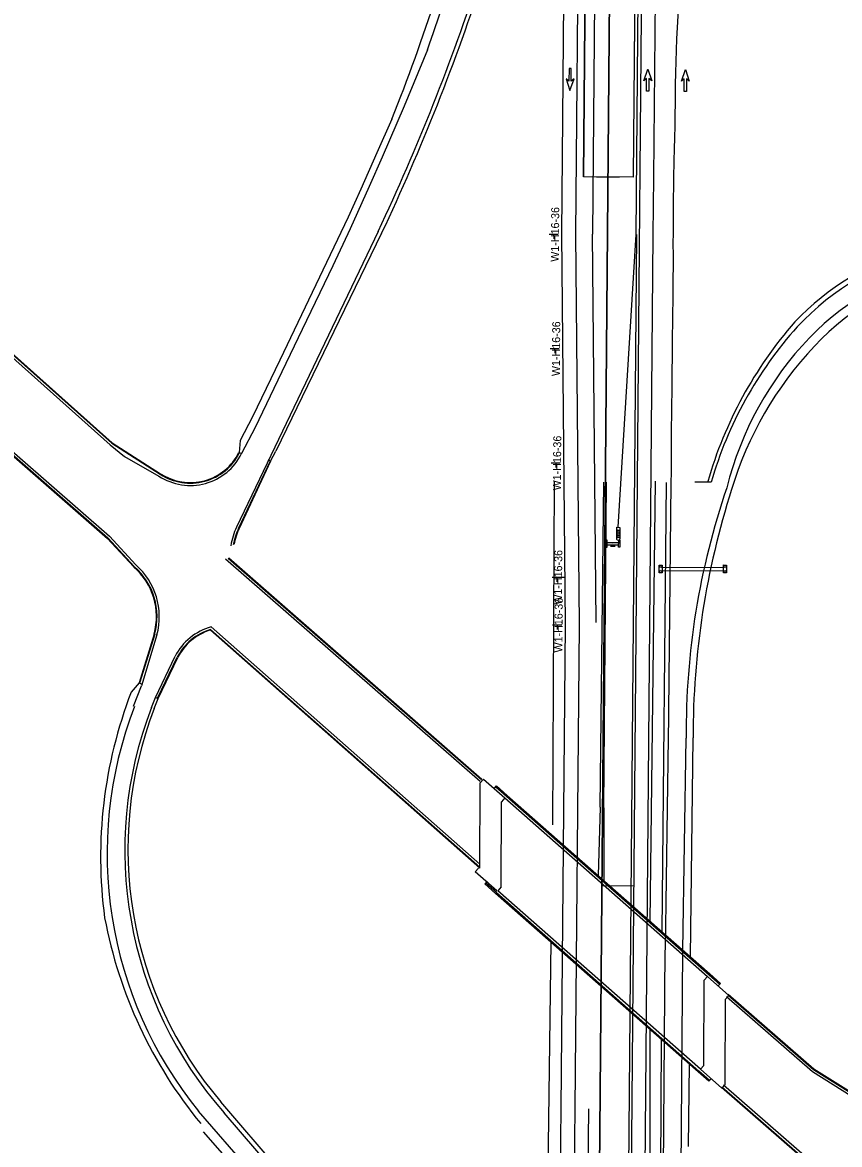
# Model space of a CAD drawing. Extents: x 1691089 to 1704871, y 694247 to 736350.
# Drawn here: x 1700893 to 1701608, y 709482 to 710464 of the extents above; entities that cross this region are included whole.
import ezdxf

# ---------------------------------------------------------------- set-up
doc = ezdxf.new("R2010")
doc.units = 0
for name, color, linetype in [('Default', 7, 'Continuous'), ('MT_P_Cells', 7, 'Continuous'), ('MT_P_Channelizing_Line', 7, 'Continuous'), ('MT_P_Drums', 7, 'Continuous'), ('MT_P_Edge_Line', 7, 'Continuous'), ('MT_P_PCB', 7, 'Continuous'), ('MT_P_Traffic_Attenuator', 7, 'Continuous'), ('MT_P_Work_Area', 7, 'Continuous'), ('PM_X_CL_Dashed', 7, 'Continuous'), ('PM_X_Edge_Line', 7, 'Continuous'), ('PV_X_Curb', 7, 'Continuous'), ('PV_X_EOP', 7, 'Continuous'), ('PV_X_Shoulder', 7, 'Continuous'), ('RW_X_CL', 7, 'Continuous'), ('SC_Scratch1', 7, 'Continuous'), ('SC_Scratch2', 7, 'Continuous'), ('SN_P_Signs', 7, 'Continuous'), ('SN_X_Truss_Overhead', 7, 'Continuous')]:
    doc.layers.add(name, color=color, linetype=linetype)

msp = doc.modelspace()

# ---------------------------------------------------------------- linework, layer by layer
at = {"layer": 'Default'}
for p, q in [((1700991.11, 709873.47), (1700991.11, 709873.47)), ((1701293.07, 709724.33), (1701293.3, 709798.79)), ((1701296.28, 709802.17), (1701293.3, 709798.79)), ((1701296.28, 709802.17), (1701315.03, 709785.63)), ((1701305.65, 709793.9), (1701307.64, 709796.15)), ((1701306.98, 709795.4), (1701316.35, 709787.13)), ((1701307.64, 709796.15), (1701317.01, 709787.88)), ((1701316.35, 709787.13), (1701493.48, 709630.96)), ((1701317.01, 709787.88), (1701494.15, 709631.71)), ((1701311.82, 709707.8), (1701312.05, 709782.26)), ((1701315.03, 709785.63), (1701312.05, 709782.26)), ((1701315.03, 709785.63), (1701492.16, 709629.46)), ((1701291.98, 709724.32), (1701289.02, 709720.93)), ((1701307.85, 709704.48), (1701289.02, 709720.93)), ((1701299.47, 709712.69), (1701297.49, 709710.44)), ((1701306.86, 709702.17), (1701297.49, 709710.44)), ((1701307.53, 709702.92), (1701298.15, 709711.19)), ((1701484, 709546), (1701306.86, 709702.17)), ((1701484.66, 709546.75), (1701307.53, 709702.92)), ((1701311.82, 709707.8), (1701308.85, 709704.42)), ((1701485.98, 709548.25), (1701308.85, 709704.42)), ((1701492.16, 709629.46), (1701489.19, 709626.08)), ((1701492.16, 709629.46), (1701510.91, 709612.92)), ((1701493.48, 709630.96), (1701502.86, 709622.69)), ((1701494.15, 709631.71), (1701503.52, 709623.44)), ((1701488.96, 709551.62), (1701489.19, 709626.08)), ((1701501.54, 709621.19), (1701503.52, 709623.44)), ((1701510.91, 709612.92), (1701507.94, 709609.55)), ((1701507.71, 709535.09), (1701507.94, 709609.55)), ((1701488.96, 709551.62), (1701485.98, 709548.25)), ((1701493.37, 709537.73), (1701484, 709546)), ((1701494.03, 709538.48), (1701484.66, 709546.75)), ((1701504.73, 709531.71), (1701485.98, 709548.25)), ((1701495.36, 709539.98), (1701493.37, 709537.73)), ((1701507.71, 709535.09), (1701504.73, 709531.71))]:
    msp.add_line(p, q, dxfattribs=at)
at = {"layer": 'MT_P_Cells'}
for p, q in [((1701370.93, 710412.57), (1701368.48, 710414.59)), ((1701368.48, 710414.59), (1701371.86, 710404.56)), ((1701371.02, 710423.57), (1701370.93, 710412.57)), ((1701373.02, 710423.55), (1701371.02, 710423.57)), ((1701372.02, 710423.56), (1701372.02, 710423.56)), ((1701372.93, 710412.55), (1701373.02, 710423.55)), ((1701436.46, 710413.01), (1701440.02, 710422.98)), ((1701438.95, 710414.99), (1701436.46, 710413.01)), ((1701438.86, 710403.99), (1701438.95, 710414.99)), ((1701440.02, 710422.98), (1701440.02, 710422.98)), ((1701440.02, 710422.98), (1701443.41, 710412.95)), ((1701440.95, 710414.97), (1701440.86, 710403.97)), ((1701443.41, 710412.95), (1701440.95, 710414.97)), ((1701469.28, 710412.73), (1701472.84, 710422.7)), ((1701471.77, 710414.7), (1701469.28, 710412.73)), ((1701471.67, 710403.71), (1701471.77, 710414.7)), ((1701472.84, 710422.7), (1701472.84, 710422.7)), ((1701472.84, 710422.7), (1701476.22, 710412.67)), ((1701473.77, 710414.69), (1701473.67, 710403.69)), ((1701476.22, 710412.67), (1701473.77, 710414.69)), ((1701371.86, 710404.56), (1701375.42, 710414.53)), ((1701375.42, 710414.53), (1701372.93, 710412.55)), ((1701371.86, 710404.56), (1701371.86, 710404.56)), ((1701440.86, 710403.97), (1701438.86, 710403.99)), ((1701439.86, 710403.98), (1701439.86, 710403.98)), ((1701473.67, 710403.69), (1701471.67, 710403.71)), ((1701472.67, 710403.7), (1701472.67, 710403.7)), ((1701404.46, 710007.09), (1701414.46, 710007)), ((1701404.48, 710009.09), (1701414.48, 710009)), ((1701411.45, 710005.53), (1701407.45, 710005.56)), ((1701408.46, 710007.05), (1701408.45, 710005.55)), ((1701409.47, 710008.04), (1701409.47, 710008.04)), ((1701410.46, 710007.03), (1701410.45, 710005.53))]:
    msp.add_line(p, q, dxfattribs=at)
for points in [[(1701403.49, 710011.09), (1701403.44, 710005.09), (1701404.44, 710005.09), (1701404.49, 710011.09)], [(1701415.49, 710010.99), (1701415.44, 710004.99), (1701414.44, 710005), (1701414.49, 710011)]]:
    msp.add_lwpolyline(points, close=True, dxfattribs=at)
at = {"layer": 'MT_P_Channelizing_Line'}
for points in [[(1701379.36, 710578.91), (1701376.78, 710278.89), (1701379.85, 709936.81)], [(1701379.85, 709936.81), (1701379.81, 709936.81), (1701376.18, 709513.9)]]:
    msp.add_lwpolyline(points, dxfattribs=at)
at = {"layer": 'MT_P_Drums'}
for p, q in [((1701391.33, 710278.81), (1701394.37, 709939.22)), ((1701422.33, 709351.5), (1701430.28, 710278.43))]:
    msp.add_line(p, q, dxfattribs=at)
at = {"layer": 'MT_P_Edge_Line'}
for p, q in [((1701445.21, 710328.34), (1701466.82, 712847.84)), ((1701444.78, 710278.3), (1701445.21, 710328.34)), ((1701437.19, 709393.09), (1701444.78, 710278.3)), ((1701364.23, 709514), (1701367.85, 709936.91))]:
    msp.add_line(p, q, dxfattribs=at)
for points in [[(1701414.35, 708961.55), (1701424.83, 709351.48), (1701474.54, 715147.93), (1701474.62, 715157.86), (1701474.71, 715167.87), (1701474.78, 715177.89), (1701474.85, 715187.92), (1701474.91, 715198.02), (1701474.96, 715207.99), (1701474.99, 715218.04), (1701475, 715228.09), (1701474.99, 715238.15), (1701474.96, 715248.3), (1701474.9, 715258.3), (1701474.81, 715268.38), (1701474.69, 715278.48), (1701474.54, 715288.57), (1701474.35, 715298.75), (1701474.12, 715308.79), (1701473.84, 715318.91), (1701473.52, 715329.03), (1701473.16, 715339.16), (1701472.74, 715349.34), (1701472.74, 715349.36)], [(1701367.85, 709936.91), (1701364.78, 710278.99), (1701390.07, 713227.64)]]:
    msp.add_lwpolyline(points, dxfattribs=at)
at = {"layer": 'MT_P_PCB'}
for p, q in [((1701429.78, 710278.47), (1701462.53, 714097.92)), ((1701414.07, 710022.33), (1701429.78, 710278.47))]:
    msp.add_line(p, q, dxfattribs=at)
at = {"layer": 'MT_P_Traffic_Attenuator'}
for p, q in [((1701412.59, 710022.34), (1701412.47, 710012.02)), ((1701412.59, 710022.34), (1701415.58, 710022.31)), ((1701415.58, 710022.31), (1701415.49, 710011.99)), ((1701415.45, 710012.96), (1701412.48, 710013.91)), ((1701415.47, 710014.54), (1701412.5, 710015.49)), ((1701412.5, 710013.05), (1701415.42, 710013.99)), ((1701412.51, 710014.64), (1701415.43, 710015.57)), ((1701415.49, 710016.09), (1701412.52, 710017.04)), ((1701412.53, 710019.27), (1701415.51, 710020.23)), ((1701415.52, 710019.18), (1701412.54, 710020.14)), ((1701415.5, 710017.64), (1701412.54, 710018.59)), ((1701412.54, 710016.19), (1701415.45, 710017.12)), ((1701412.56, 710017.74), (1701415.47, 710018.67))]:
    msp.add_line(p, q, dxfattribs=at)
msp.add_arc((1701413.99, 710012.64), 1.64, 202.38552, 336.63188, dxfattribs=at)
at = {"layer": 'MT_P_Work_Area'}
msp.add_line((1701415.21, 710328.6), (1701395.21, 710328.77), dxfattribs=at)
for points in [[(1701423.28, 715347.21), (1701423.69, 715337.24), (1701424.05, 715327.35), (1701424.37, 715317.46), (1701424.63, 715307.55), (1701424.86, 715297.71), (1701425.05, 715287.73), (1701425.2, 715277.8), (1701425.32, 715267.88), (1701425.4, 715257.94), (1701425.46, 715248.07), (1701425.49, 715238.05), (1701425.5, 715228.1), (1701425.49, 715218.14), (1701425.46, 715208.18), (1701425.41, 715198.28), (1701425.35, 715188.24), (1701425.29, 715178.26), (1701425.21, 715168.27), (1701425.13, 715158.28), (1701425.04, 715148.35), (1701383.71, 710328.87)], [(1701466.74, 715349.1), (1701466.74, 715349.09), (1701467.16, 715338.93), (1701467.53, 715328.83), (1701467.85, 715318.73), (1701468.12, 715308.64), (1701468.35, 715298.62), (1701468.54, 715288.47), (1701468.69, 715278.39), (1701468.81, 715268.32), (1701468.9, 715258.26), (1701468.96, 715248.27), (1701468.99, 715238.14), (1701469, 715228.09), (1701468.99, 715218.05), (1701468.96, 715208.01), (1701468.91, 715198.05), (1701468.85, 715187.96), (1701468.78, 715177.94), (1701468.71, 715167.92), (1701468.62, 715157.91), (1701468.54, 715147.98), (1701427.21, 710328.49)], [(1701459.42, 714084.32), (1701427.21, 710328.49), (1701383.71, 710328.87), (1701425.04, 715148.35)]]:
    msp.add_lwpolyline(points, dxfattribs=at)
at = {"layer": 'PM_X_CL_Dashed'}
msp.add_line((1701376.18, 709513.9), (1701371.88, 709153.62), dxfattribs=at)
at = {"layer": 'PM_X_Edge_Line'}
for p, q in [((1701458.1, 709832.7), (1701460.45, 710061.44)), ((1701455.32, 709652.66), (1701458.19, 709838.29)), ((1701453.58, 709431.6), (1701455.27, 709652.54)), ((1701468.96, 709431.48), (1701470.65, 709652.42)), ((1701359.3, 709110.99), (1701364.23, 709514)), ((1701388.22, 709513.8), (1701383.88, 709153.62))]:
    msp.add_line(p, q, dxfattribs=at)
for points in [[(1701464.27, 710409.79), (1701464.41, 710419.77), (1701464.64, 710429.76), (1701464.91, 710439.73), (1701465.31, 710449.71), (1701465.79, 710459.68), (1701466.41, 710469.68), (1701467.07, 710479.62), (1701468.02, 710489.55), (1701469.01, 710499.53), (1701470.02, 710509.54), (1701470.96, 710519.53), (1701471.99, 710529.45), (1701473.06, 710539.38), (1701474.3, 710549.25), (1701474.72, 710552.39)], [(1701460.45, 710061.44), (1701460.55, 710070.28), (1701460.61, 710080.28), (1701460.68, 710090.28), (1701460.78, 710100.3), (1701460.81, 710110.3), (1701460.92, 710120.29), (1701461, 710130.29), (1701461.12, 710140.29), (1701461.19, 710150.29), (1701461.54, 710180.28), (1701461.66, 710190.28), (1701461.79, 710200.28), (1701461.9, 710210.28), (1701462.01, 710220.28), (1701462.09, 710230.28), (1701462.3, 710260.31), (1701462.24, 710270.31), (1701462.31, 710280.28), (1701462.38, 710290.28), (1701462.44, 710300.28), (1701462.54, 710310.25), (1701462.77, 710320.26), (1701462.81, 710330.27), (1701462.98, 710340.29), (1701463, 710343.26), (1701463.29, 710353.24), (1701463.49, 710363.24), (1701463.77, 710373.24), (1701463.93, 710383.27), (1701464.1, 710393.28), (1701464.21, 710403.3), (1701464.26, 710409.81)]]:
    msp.add_lwpolyline(points, dxfattribs=at)
at = {"layer": 'PV_X_Curb'}
for p, q in [((1700971.12, 710095.92), (1701013.46, 710068.83)), ((1700971.45, 710096.29), (1701013.73, 710069.25)), ((1701109.54, 710080.32), (1701082, 710021.63)), ((1701110, 710080.1), (1701082.46, 710021.42)), ((1700990.31, 709987.7), (1700967.12, 710012.88)), ((1700990.68, 709988.04), (1700967.48, 710013.22)), ((1701008.1, 709928.91), (1700994.92, 709886.17)), ((1701008.59, 709928.78), (1700995.23, 709886.05)), ((1701057.41, 709932.42), (1701293.07, 709724.33)), ((1701057.54, 709932.98), (1701293.07, 709724.99)), ((1701011.02, 709872.9), (1701028.3, 709908.62)), ((1701011.53, 709872.7), (1701028.75, 709908.39)), ((1701584.9, 709548.09), (1701629.12, 709520.4)), ((1701585.16, 709548.52), (1701629.38, 709520.84))]:
    msp.add_line(p, q, dxfattribs=at)
for points in [[(1700673.51, 710361.66), (1700971.04, 710095.97)], [(1700673.84, 710362.04), (1700971.37, 710096.34)], [(1700628.16, 710308.99), (1700967.31, 710012.69)], [(1700628.48, 710309.37), (1700967.64, 710013.07)], [(1701072.81, 709995.47), (1701294.5, 709801.79)], [(1701073.35, 709995.67), (1701294.83, 709802.17)], [(1701510, 709613.52), (1701584.9, 709548.09)], [(1701510.33, 709613.9), (1701585.16, 709548.52)], [(1701504.52, 709532.66), (1701595.73, 709452.97)], [(1701504.84, 709533.04), (1701596.01, 709453.39)]]:
    msp.add_lwpolyline(points, dxfattribs=at)
for centre, radius, start, end in [((1701039.79, 710108.96), 48, 236.73099, 333.65872), ((1701039.79, 710108.96), 47.5, 236.73099, 333.64609), ((1701134.52, 709997), 58, 154.87152, 170.01912), ((1701134.52, 709997), 57.5, 154.87152, 169.7386), ((1700952.67, 709944.21), 57.5, 344.57519, 48.85797), ((1700952.67, 709944.21), 58, 344.57519, 48.85797), ((1701071.13, 709886.94), 48, 106.4476, 153.15416), ((1701071.13, 709886.94), 47.5, 106.78063, 153.15416)]:
    msp.add_arc(centre, radius, start, end, dxfattribs=at)
at = {"layer": 'PV_X_EOP'}
for p, q in [((1701446.54, 715148.22), (1701323.36, 700783.77)), ((1701446.54, 715148.22), (1701323.36, 700783.77)), ((1701446.54, 715148.22), (1701323.36, 700783.77)), ((1701446.54, 715148.22), (1701323.36, 700783.77)), ((1701204.1, 710281.24), (1701080.19, 710022.48)), ((1701570.63, 710197.69), (1701570.57, 710197.63)), ((1700969.71, 710094.48), (1700982.17, 710084.38)), ((1700982.17, 710084.38), (1701012.36, 710067.16)), ((1701442.11, 709677.59), (1701446.66, 710062.61)), ((1701452.37, 709668.55), (1701456.39, 710061.49)), ((1701495.4, 710061.93), (1701481.15, 710061.91)), ((1700992.15, 709989.39), (1700968.96, 710014.57)), ((1701058.04, 709935.2), (1701293.08, 709727.65)), ((1701010.51, 709928.25), (1700996.97, 709883.67)), ((1701009.2, 709873.6), (1701026.52, 709909.52)), ((1700990.15, 709866.02), (1700996.97, 709883.67)), ((1701005.79, 709864.77), (1701009.2, 709873.6)), ((1701470.65, 709652.42), (1701473.52, 709838.05)), ((1701441.64, 709583.34), (1701441.64, 709387.21)), ((1701450.77, 709387.21), (1701451.91, 709574.29)), ((1701583.87, 709546.33), (1701628.07, 709518.66)), ((1701210.68, 709323.85), (1701047.02, 709511.5)), ((1701228.17, 709326.42), (1701069.34, 709510.19))]:
    msp.add_line(p, q, dxfattribs=at)
for points in [[(1701247.27, 710440.07), (1701226.92, 710390.69), (1701207.69, 710346.14), (1701196.18, 710320.33), (1701179.47, 710283.57), (1701164.35, 710250.99), (1701137.56, 710195.44), (1701112.77, 710143.68), (1701096.48, 710109.8), (1701084.62, 710086.81)], [(1701215.93, 710379.42), (1701202.83, 710349.77), (1701188.79, 710318.04), (1701177.9, 710293.56), (1701118.03, 710168.6), (1701094.19, 710119.09), (1701083.44, 710098.42)], [(1700672.18, 710360.17), (1700969.71, 710094.48)], [(1700629.8, 710310.88), (1700968.96, 710014.57)], [(1701070.65, 709994.7), (1701293.19, 709800.28)], [(1701508.68, 709612.02), (1701583.87, 709546.33)], [(1701506.16, 709534.55), (1701597.29, 709454.93)]]:
    msp.add_lwpolyline(points, dxfattribs=at)
for centre, radius, start, end in [((1700032.25, 710871.58), 1289.37, 340.44777, 348.08356), ((1699818.13, 710945.69), 1508.14, 337.94619, 346.63736), ((1699464.5, 711101.87), 1923.44, 334.74509, 341.95963), ((1701741.81, 710037.4), 234.52, 4.97857, 136.90374), ((1701740.97, 710035.43), 220.9, 350.82419, 136.25948), ((1701830.56, 709964.94), 348.91, 138.15799, 163.8607), ((1701792.07, 709986.54), 291.62, 136.25948, 166.0196), ((1701039.79, 710108.96), 50, 236.73099, 333.7067), ((1702131.08, 709843.57), 657.58, 161.06185, 180.48104), ((1701134.52, 709997), 60, 154.87152, 171.10224), ((1700952.67, 709944.21), 60, 344.57519, 48.85797), ((1701071.13, 709886.94), 50, 105.17101, 153.15416), ((1701324.17, 709736.9), 357.24, 158.8647, 219.11924), ((1701329.19, 709739.75), 346.73, 158.8647, 221.45803)]:
    msp.add_arc(centre, radius, start, end, dxfattribs=at)
at = {"layer": 'PV_X_Shoulder'}
for p, q in [((1701207.15, 710279.51), (1701114.7, 710088.94)), ((1701568.5, 710202.03), (1701568.43, 710201.95)), ((1701083.44, 710098.42), (1701082.36, 710087.88)), ((1701082.36, 710087.88), (1701084.62, 710086.81)), ((1701110, 710080.1), (1701107.73, 710081.17)), ((1701110, 710080.1), (1701114.7, 710088.94)), ((1701356.77, 709762.2), (1701358.45, 710062.33)), ((1701398.26, 709777.69), (1701401.61, 710061.81)), ((1701401.51, 709777.04), (1701403.92, 710061.77)), ((1701492.5, 710062.69), (1701492.4, 710062.38)), ((1700994.92, 709886.17), (1700988.05, 709878.11)), ((1700994.92, 709886.17), (1700997.44, 709885.2)), ((1701008.14, 709863.74), (1701011.53, 709872.7)), ((1701477.2, 709646.65), (1701479.52, 709838.06)), ((1701398.26, 709777.69), (1701396.43, 709717.87)), ((1701401.51, 709777.04), (1701401.51, 709713.38)), ((1701427.89, 709708.43), (1701399.9, 709708.67)), ((1701351.52, 709368.75), (1701355.4, 709659.38)), ((1701475.63, 709480.79), (1701476.31, 709552.77)), ((1701242.08, 709315.76), (1701066.47, 709519.73)), ((1701211.68, 709311.85), (1701051.17, 709493.55))]:
    msp.add_line(p, q, dxfattribs=at)
msp.add_lwpolyline([(1701009.2, 709873.6), (1701011.53, 709872.7)], dxfattribs=at)
for centre, radius, start, end in [((1699445.12, 711109.2), 1947.59, 334.78554, 342.00007), ((1701741.23, 710036.81), 239.02, 17.72313, 136.29709), ((1701742.81, 710035.29), 214.05, 348.84239, 137.20471), ((1701844.79, 709960.91), 366.7, 138.88922, 163.93714), ((1701813.41, 709965.33), 313.4, 136.58766, 163.29911), ((1702192.9, 709839.1), 735.23, 162.29504, 162.35768), ((1702191.68, 709838.88), 712.17, 162.30077, 180.06572), ((1701362.53, 709733.98), 401.26, 158.94911, 187.61886), ((1701326.32, 709740.74), 341.13, 158.8647, 220.38141), ((1701359.11, 709755.2), 401.26, 190.68917, 219.35892)]:
    msp.add_arc(centre, radius, start, end, dxfattribs=at)
at = {"layer": 'RW_X_CL'}
msp.add_line((1701323.36, 700783.77), (1701446.54, 715148.22), dxfattribs=at)
at = {"layer": 'SC_Scratch2'}
msp.add_line((1701360.26, 709978.78), (1701367.48, 709978.84), dxfattribs=at)
msp.add_lwpolyline([(1701391.78, 710278.76), (1701433.54, 715148.28), (1701433.62, 715158.21), (1701433.71, 715168.2), (1701433.79, 715178.19), (1701433.85, 715188.18), (1701433.91, 715198.24), (1701433.96, 715208.15), (1701433.99, 715218.13), (1701434, 715228.1), (1701433.99, 715238.07), (1701433.96, 715248.11), (1701433.9, 715258), (1701433.82, 715267.96), (1701433.7, 715277.92), (1701433.55, 715287.87), (1701433.36, 715297.89), (1701433.13, 715307.77), (1701432.86, 715317.71), (1701432.55, 715327.64), (1701432.19, 715337.57), (1701431.78, 715347.57), (1701431.78, 715347.58)], dxfattribs=at)
at = {"layer": 'SN_P_Signs'}
for p, q in [((1701353.57, 710278.73), (1701361.57, 710278.8)), ((1701357.57, 710278.77), (1701357.61, 710274.77)), ((1701354.47, 710178.74), (1701362.47, 710178.81)), ((1701358.47, 710178.77), (1701358.5, 710174.77)), ((1701355.37, 710078.74), (1701363.36, 710078.81)), ((1701359.37, 710078.78), (1701359.4, 710074.78)), ((1701356.26, 709978.74), (1701364.26, 709978.82)), ((1701360.26, 709978.78), (1701360.3, 709974.78)), ((1701356.64, 709936.94), (1701364.64, 709937.01)), ((1701360.64, 709936.97), (1701360.67, 709932.97))]:
    msp.add_line(p, q, dxfattribs=at)
at = {"layer": 'SN_X_Truss_Overhead'}
for p, q in [((1701451.2, 709985.86), (1701451.2, 709985.86)), ((1701452.44, 709984.4), (1701506.22, 709984.46)), ((1701452.46, 709987.32), (1701506.24, 709987.37)), ((1701507.48, 709985.92), (1701507.48, 709985.92))]:
    msp.add_line(p, q, dxfattribs=at)
for points in [[(1701449.92, 709982.41), (1701449.98, 709989.33), (1701452.48, 709989.31), (1701452.42, 709982.39)], [(1701506.2, 709982.47), (1701506.26, 709989.39), (1701508.76, 709989.36), (1701508.7, 709982.45)]]:
    msp.add_lwpolyline(points, close=True, dxfattribs=at)
for centre in [(1701451.18, 709983.65), (1701451.22, 709988.07), (1701507.46, 709983.71), (1701507.5, 709988.12)]:
    msp.add_circle(centre, 1, dxfattribs=at)

# ---------------------------------------------------------------- texts
at = {"layer": 'SC_Scratch1'}
for p in [(1701362.09, 710254.6), (1701362.99, 710154.6), (1701363.88, 710054.61), (1701364.78, 709954.61), (1701365.16, 709912.8)]:
    msp.add_text('W1-H16-36', height=7, rotation=89.5087, dxfattribs=at).set_placement(p)

doc.saveas('drawing.dxf')
